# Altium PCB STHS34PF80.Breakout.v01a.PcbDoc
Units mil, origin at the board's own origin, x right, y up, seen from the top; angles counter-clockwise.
Board outline 705 x 405 mil, 4 copper layers (L1, L2, L3, L4), stack 61.109 mil thick; 13 components, 5 nets, 26 pads, 28 vias.
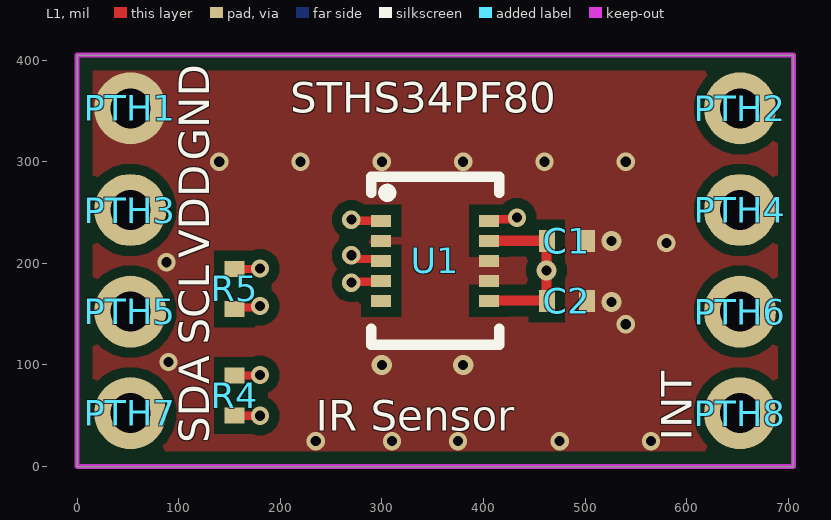
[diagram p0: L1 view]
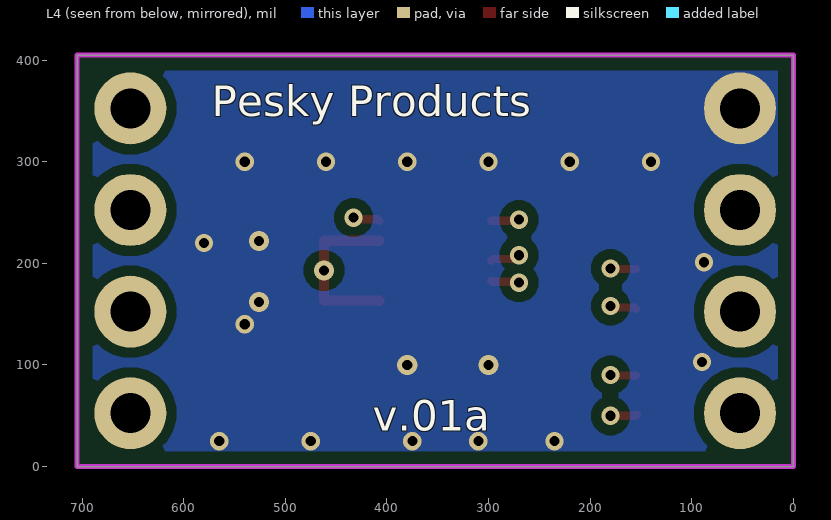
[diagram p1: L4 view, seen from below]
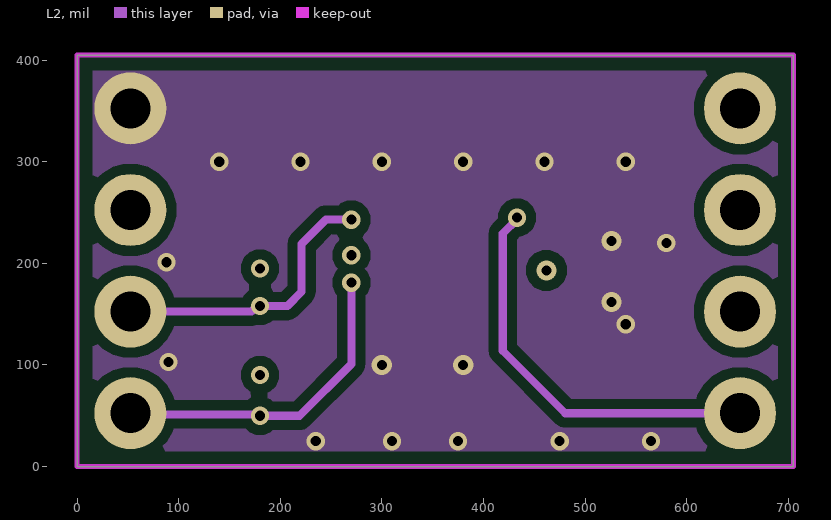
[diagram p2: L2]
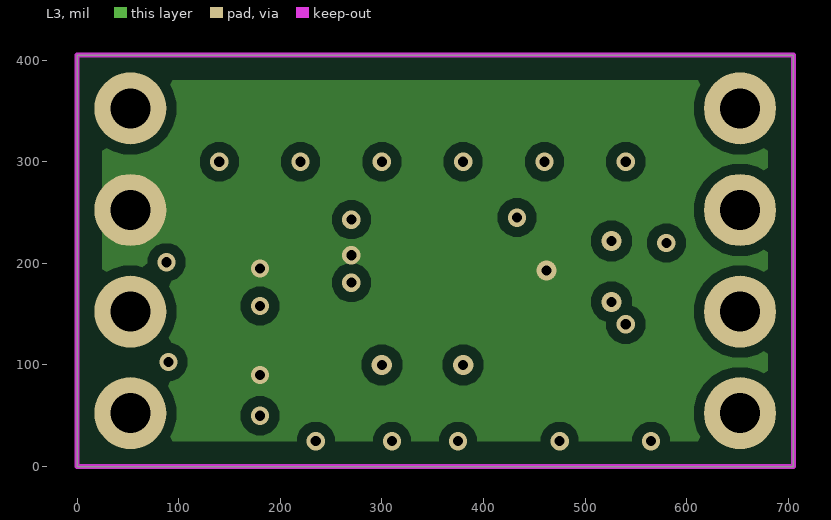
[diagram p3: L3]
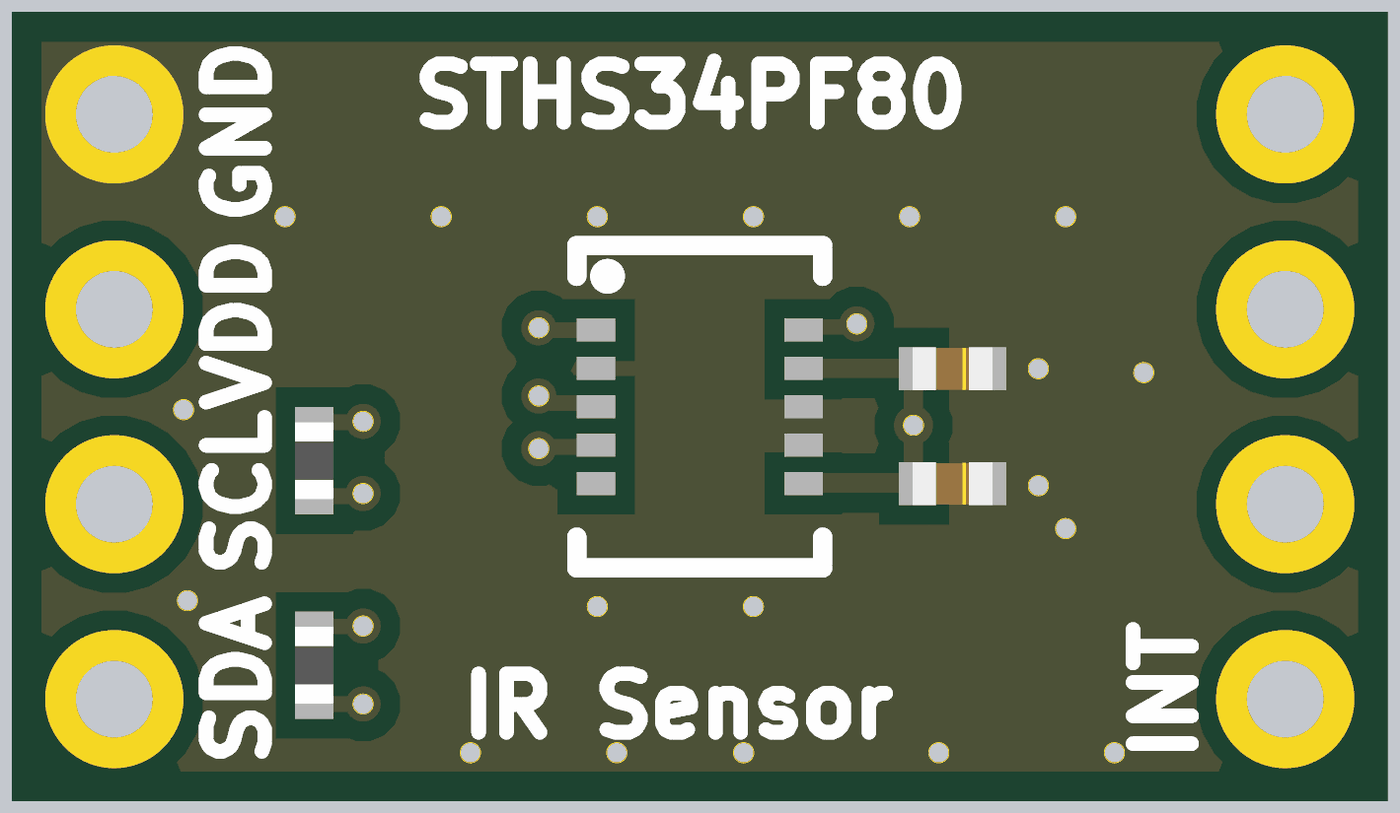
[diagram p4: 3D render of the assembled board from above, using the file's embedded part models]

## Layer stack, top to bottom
Top Solder: solder mask 0.1, Solder Resist, Dk 1
L1: signal copper 0.1772
Prepeg12: dielectric 6.7, FR408, Dk 3.66
L2: signal copper 0.1772
Core: dielectric 47, FR-4, Dk 3.66
L3: signal copper 0.1772
Prepeg34: dielectric 6.7, FR408, Dk 3.66
L4: signal copper 0.1772
Bottom Solder: solder mask 0.1, Solder Resist, Dk 1

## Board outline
0,0 705,0 705,405 0,405

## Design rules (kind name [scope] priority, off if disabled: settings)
BoardOutlineClearance [All] p1: gap=15 ignorepadtopadclearanceinfootprint=FALSE
Clearance "Clearance Polygons" [InPolygon] p1: gap=10 ignorepadtopadclearanceinfootprint=FALSE except(0: Arc-Hole Track-Hole SMDPad-Hole THPad-Hole Via-Hole Fill-Hole Poly-Hole Region-Hole Text-Hole)
Clearance [All] p2: gap=5 ignorepadtopadclearanceinfootprint=TRUE except(0: Arc-Hole Track-Hole SMDPad-Hole THPad-Hole Via-Hole Fill-Hole Poly-Hole Region-Hole Text-Hole; 8: Arc-Arc Arc-Track Track-Track)
ComponentClearance "HM-TRP & UFL" [InComponent('X1') vs InComponent('U1')] p1: gap=0 collisioncheckmode=3 verticalgap=0 showdistances=FALSE
ComponentClearance [All] p2: gap=1 collisioncheckmode=3 verticalgap=1 showdistances=FALSE
DiffPairsRouting [All] p1: maxlimit=393.7 minlimit=5 mostfreqgap=8 toplayer_minwidth=5 toplayer_maxwidth=15 toplayer_prefwidth=8 midlayer1_minwidth=5 midlayer1_maxwidth=15 midlayer1_prefwidth=8 midlayer2_minwidth=5 midlayer2_maxwidth=15 midlayer2_prefwidth=8 bottomlayer_minwidth=5 bottomlayer_maxwidth=15 bottomlayer_prefwidth=8 maxuncoupledlength=500
HoleSize [All] p1: absolutevalues=TRUE maxlimit=265 minlimit=10 maxpercent=80.000 minpercent=20.000
HoleToHoleClearance [All] p1: gap=10 allowstackedmicrovias=FALSE
MinimumAnnularRing [All] p1: minimumring=4
MinimumSolderMaskSliver [All] p1: minsoldermaskwidth=0
PlaneClearance [All] p1: clearance=10
PlaneConnect [All] p1: planeconnectstyle=Relief reliefexpansion=4 reliefentries=4 reliefconductorwidth=6 reliefairgap=6
PolygonConnect "Via connect style" [isVia] p1: connectstyle=Direct reliefconductorwidth=10 reliefentries=4 polygonreliefangle="90 Angle" airgapwidth=10
PolygonConnect [All] p2: connectstyle=Direct reliefconductorwidth=10 reliefentries=4 polygonreliefangle="90 Angle" airgapwidth=6
RoutingCorners [All] p1: cornerstyle=45-Degree minsetback=49.21 maxsetback=49.21
RoutingVias [All] p1: holewidth=10 width=18 viastyle="Through Hole" minholewidth=10 minwidth=18 maxholewidth=100 maxwidth=114
SilkToSilkClearance [All] p1: silktosilkclearance=0
SilkToSolderMaskClearance [IsPad] p1: minsilkscreentomaskgap=5 clearancetoexposedcopper=TRUE
SolderMaskExpansion [IsVia] p1: expansion=2.5 istentingtop=TRUE
Width GND [InNet('GND')] p1: maxlimit=30 minlimit=10 preferedwidth=20
Width Power [InNetClass('Power')] p2: maxlimit=40 minlimit=20 preferedwidth=30
Width 3V3 [InNetClass('3V3')] p3: maxlimit=30 minlimit=10 preferedwidth=20
Width [All] p4: maxlimit=400 minlimit=6 preferedwidth=8
20 further rules are at their usual default settings.

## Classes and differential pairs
component class STHS34PF80.Breakout.v01a: C1 C2 PTH1 PTH2 PTH3 PTH4 PTH5 PTH6 PTH7 PTH8 R4 R5

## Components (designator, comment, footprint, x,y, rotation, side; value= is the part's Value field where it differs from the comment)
C1 "0.1 uF" 402Cap 482,222 r180 top
C2 "1 uF" 402Cap 482,163 r180 top
PTH1 "PTH2.54" PTH2.54 52.5,352.5 r90 top
PTH2 "PTH2.54" PTH2.54 652.5,352.5 r90 top
PTH3 "PTH2.54" PTH2.54 52.5,252.5 r90 top
PTH4 "PTH2.54" PTH2.54 652.5,252.5 r90 top
PTH5 "PTH2.54" PTH2.54 52.5,152.5 r90 top
PTH6 "PTH2.54" PTH2.54 652.5,152.5 r90 top
PTH7 "PTH2.54" PTH2.54 52.5,52.5 r90 top
PTH8 "PTH2.54" PTH2.54 652.5,52.5 r90 top
R4 "4K7" 402RES 155,70 r90 top
R5 "4K7" 402RES 155,175 r90 top
U1 "STHS34PF80" STHS34PF80TR 352.5,202.5 r0 top

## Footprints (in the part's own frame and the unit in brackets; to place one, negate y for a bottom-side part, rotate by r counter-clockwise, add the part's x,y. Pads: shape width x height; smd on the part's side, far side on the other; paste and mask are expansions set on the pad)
402Cap [mm] "0402 package capacitor"
  rect 0.4x0.559 smd: 1(-0.5,0) 2(0.5,0)
  body extent -0.52,-0.28 0.52,0.28, height 0.58
402RES [mm] "0402 package resistor"
  rect 0.4x0.5 smd: 1(-0.504,-0.001) 2(0.496,-0.001)
  body extent -0.5,-0.25 0.5,0.25, height 0.41
PTH2.54 [mm] "Standard 0.1\" plated through hole"
  round 1.8 hole 1: 1(0,0)
STHS34PF80TR [mm] "OLGA-10L 3.2 x 4.2 x 1.455 mm package"
  rect 0.5x0.3 smd: 1(-1.35,1) 2(-1.35,0.5) 3(-1.35,0) 4(-1.35,-0.5) 5(-1.35,-1) 6(1.35,-1) 7(1.35,-0.5) 8(1.35,0) 9(1.35,0.5) 10(1.35,1)
  silkscreen extent -1.6,-2.1 1.6,2.1, body extent -1.6,-2.1 1.6,2.1, height 1.5

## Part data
C1: library part CL05B104KO5NNNC, "0402 0.1 uF Ceramic Capacitor, Multilayer, Ceramic, 16V, 10% +Tol, 10% -Tol, X7R, 15% TC, 0.1uF, Surface Mount, 0402", Capacitance=100nF, Capacitor Type=Ceramic, Manufacturer=Samsung, Max Operating Temperature=125°C, Min Operating Temperature=-55°C, Negative Tolerance=10%, Package Shape=Rectangular, Package Style=SMTMeter, Rated DC Voltage (URdc)=16V, Supplier Part Number 1=1276-1001-1-ND, Temperature Characteristics Code=X7R
C2: library part GRT155R61C105KE01D, "0402 1 uF Ceramic Capacitor, Multilayer, Ceramic, 16V, 10% +Tol, 10% -Tol, X5R, 15% TC, 1uF, Surface Mount, 0402", Capacitance=1uF, Capacitor Type=Ceramic, Manufacturer=Murata, Max Operating Temperature=85°C, Min Operating Temperature=-55°C, Negative Tolerance=10%, Package Shape=Rectangular, Rated DC Voltage (URdc)=16V, Supplier Part Number 1=490-12255-1-ND, Temperature Characteristics Code=X5R
PTH1 PTH2 PTH3 PTH4 PTH5 PTH6 PTH7 PTH8: "Standard 0.1\" plated through hole for pin headers"
R4 R5: library part RC0402FR-074K7P, "0402 4K7 Fixed Resistor, Metal Glaze/thick Film, 0.0625W, 4700ohm, 50V, 1% +/-Tol, 150ppm/Cel, Surface Mount, 0402", Manufacturer=Yageo, Max Operating Temperature=155°C, Min Operating Temperature=-55°C, Package Shape=Rectangular, Rated Power Dissipation (P)=62.5mW, Rated Temperature=70°C, Resistance=4.7kR, Resistor Type="FIXED RESISTOR", Supplier Part Number 1=YAG1272CT-ND, Temperature Coefficient=150ppm/°C, Tolerance=1%, Working Voltage=50V
U1: "Infrared Detectors Low-power, high-sensitivity infrared sensor for presence and motion detection", Manufacturer=STMicroelectronics, Manufacturer Part Number=STHS34PF80TR, Supplier Part Number=511-STHS34PF80TR

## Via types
v1: diameter 18, hole 10, L1 to L4, tented both sides, 23 vias
v2: diameter 20, hole 10, L1 to L4, tented both sides, 5 vias

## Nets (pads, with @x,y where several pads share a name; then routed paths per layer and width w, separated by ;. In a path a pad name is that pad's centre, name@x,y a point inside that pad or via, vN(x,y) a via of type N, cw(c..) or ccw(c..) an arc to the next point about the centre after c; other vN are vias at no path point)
GND: C1.1 C2.1 PTH1.1 U1.2 U1.7 U1.8
  other v1: 235,25 310,25 375,25 475,25 565,25 90,103 540,140 88,201 580,220 140,300 220,300 300,300 380,300 460,300 540,300
  other v2: 300,100 380,100 526,162 526,222
INT: PTH8.1 U1.10 | length 422.5
  L1 w8: U1.10@407.62,241.87 409.18,243.43 431.43,243.43 v1(433,245)
  L2 w8: v1(433,245) 433,243.3 419,229.3 419,114 480.5,52.5 PTH8.1
SCL: PTH5.1 R5.1 U1.1 | length 338.4
  L1 w8: R5.1 156.47,156.57 178.57,156.57 v1(180,158) ; v1(270,243) 271.13,241.87 U1.1@297.38,241.87
  L1 w10: PTH5.1 PTH5.1@53.82,153.82
  L2 w8: PTH5.1 171.79,152.5 177.29,158 v1(180,158) 207,158 221,172 221,219 245,243 v1(270,243)
SDA: PTH7.1 R4.1 U1.4 | length 377.1
  L1 w8: R4.1@153.86,51.32 R4.1 155.18,50 v1(180,50) v1@181,50 ; v1(270,181) 270.91,181.91 296.47,181.91 U1.4@297.38,182.82
  L1 w10: PTH7.1 PTH7.1@53.68,51.32
  L2 w8: PTH7.1 53.75,51.25 178.75,51.25 v1(180,50) 219,50 270,101 v1(270,181)
VDD: C1.2 C2.2 PTH3.1 R4.2 R5.2 U1.3 U1.6 U1.9 | length 247.7
  L1 w8: R4.2 155.28,89.76 179.76,89.76 v1(180,90) ; R5.2 179.51,194.51 v1(180,195) ; v1(270,208) 272.71,208 276.3,204.41 295.48,204.41 U1.3@297.38,202.5
  L1 w10: U1.6@407.62,163.13 407.9,163.41 461.72,163.41 462,163.69 v2(462,193) 462,222.31 461.93,222.25 407.68,222.25 U1.9@407.62,222.18
pads on no net: PTH2.1 PTH4.1 PTH6.1 U1.5

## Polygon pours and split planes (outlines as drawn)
GND on L1 "bottomSignal" (solid, pour order 7): 0,405 705,405 705,0 0,0
GND on L2 "bottomSignal" (solid, pour order 8): 0,405 705,405 705,0 0,0
GND on L4 "bottomSignal" (solid, pour order 6): 705,405 705,0 0,0 0,405
VDD on L3 "bottomSignal" (solid, pour order 9): 25,380 680,380 680,25 25,25

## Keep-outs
Keep-Out Layer:
  the board outline again, w5

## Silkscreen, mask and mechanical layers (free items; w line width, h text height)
Top Overlay:
  text "STHS34PF80" at 210.05,348 h30
  text "GND" at 130,301.01 h30 r90
  text "VDD" at 130,205.01 h30 r90
  text "SCL" at 130,120.01 h30 r90
  text "IR Sensor" at 235.04,35 h30
  text "INT" at 605,25.51 h30 r90
  text "SDA" at 130,23.01 h30 r90
Bottom Overlay:
  text "Pesky Products" at 572.43,345 h30
  text "v.01a" at 413.98,35 h30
